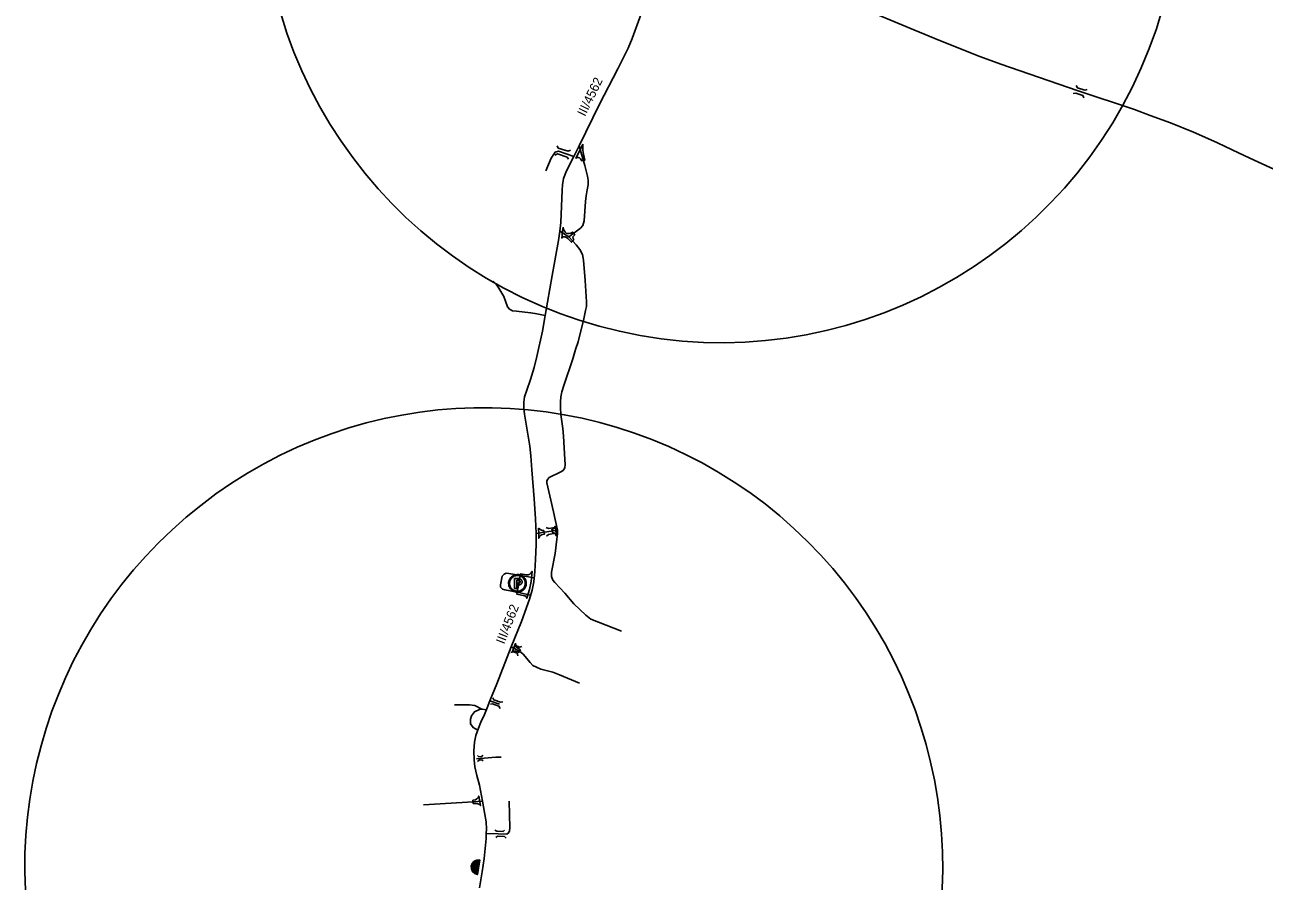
# Model space of a CAD drawing. Extents: x -546703 to -534152, y -1046534 to -1035676.
# Drawn here: x -544141 to -542791, y -1041629 to -1040697 of the extents above; entities that cross this region are included whole.
import ezdxf

# ---------------------------------------------------------------- set-up
doc = ezdxf.new("R2010")
doc.units = 0
for name, color, linetype in [('Vrstva 11', 7, 'Continuous'), ('Vrstva 14', 7, 'Continuous'), ('Vrstva 19', 7, 'Continuous'), ('Vrstva 23', 7, 'Continuous'), ('Vrstva 26', 7, 'Continuous'), ('Vrstva 4', 7, 'Continuous'), ('Vrstva 46', 7, 'Continuous'), ('Vrstva 7', 7, 'Continuous'), ('Vrstva 8', 7, 'Continuous')]:
    doc.layers.add(name, color=color, linetype=linetype)

msp = doc.modelspace()

# ---------------------------------------------------------------- linework, layer by layer
at = {"layer": 'Vrstva 11'}
for points in [[(-543542.6, -1041327.3), (-543529.7, -1041339.7), (-543524, -1041343.8), (-543490.8, -1041357.1)], [(-543706.6, -1041546), (-543652.5, -1041542.9), (-543642.2, -1041542.3)]]:
    msp.add_lwpolyline(points, dxfattribs=at)
msp.add_lwpolyline([(-543652.6, -1041541.2), (-543649.9, -1041540.7), (-543648.4, -1041539.8), (-543647, -1041538.3), (-543646.3, -1041536.6), (-543645.2, -1041542.9), (-543644.4, -1041547), (-543645.6, -1041545.8), (-543647.1, -1041545.2), (-543648.9, -1041544.8), (-543652.5, -1041544.7)], close=True, dxfattribs=at)
at = {"layer": 'Vrstva 14'}
msp.add_line((-543634, -1041432.8), (-543623.6, -1041436.7), dxfattribs=at)
msp.add_lwpolyline([(-543648.8, -1041495.9), (-543627.5, -1041494.1), (-543624.5, -1041494.1), (-543621.9, -1041494.4)], dxfattribs=at)
at = {"layer": 'Vrstva 19'}
msp.add_lwpolyline([(-543604, -1041312.4), (-543604.8, -1041316.6), (-543595.9, -1041318.5), (-543594.7, -1041319.2), (-543594.1, -1041320.1), (-543594, -1041321.2), (-543591, -1041311.7), (-543589.3, -1041303), (-543588.2, -1041291.9), (-543589.4, -1041294), (-543590.5, -1041294.9), (-543592.5, -1041295.6), (-543594.1, -1041295.5), (-543600.7, -1041294.5), (-543603.4, -1041309.2)], close=True, dxfattribs=at)
at = {"layer": 'Vrstva 23'}
for points in [[(-543654.4, -1041612.9), (-543653.3, -1041609.9), (-543651.2, -1041607.6), (-543648.3, -1041606.3), (-543645.1, -1041606.2), (-543647.7, -1041622.2), (-543650.6, -1041621.1), (-543653, -1041618.9), (-543654.3, -1041616)], [(-543653.8, -1041613), (-543652.8, -1041610.2), (-543650.8, -1041608.1), (-543648.2, -1041606.9), (-543645.8, -1041606.8), (-543648.1, -1041621.3), (-543650.3, -1041620.5), (-543652.5, -1041618.6), (-543653.7, -1041615.9)], [(-543653.2, -1041613.1), (-543652.3, -1041610.6), (-543650.4, -1041608.6), (-543648, -1041607.5), (-543646.6, -1041607.4), (-543648.6, -1041620.5), (-543650, -1041620), (-543652, -1041618.2), (-543653.1, -1041615.8)], [(-543652.6, -1041613.2), (-543651.7, -1041610.9), (-543650.1, -1041609.1), (-543647.9, -1041608.1), (-543647.3, -1041608), (-543649.1, -1041619.7), (-543649.7, -1041619.5), (-543651.5, -1041617.8), (-543652.5, -1041615.6)], [(-543652, -1041613.3), (-543651.2, -1041611.2), (-543649.7, -1041609.6), (-543648, -1041608.8), (-543649.6, -1041618.8), (-543651, -1041617.5), (-543651.9, -1041615.5)], [(-543651.4, -1041613.4), (-543650.7, -1041611.5), (-543649.4, -1041610.1), (-543648.8, -1041609.8), (-543650, -1041617.6), (-543650.5, -1041617.1), (-543651.3, -1041615.3)], [(-543650.8, -1041613.5), (-543650.2, -1041611.8), (-543649.6, -1041611.2), (-543650.3, -1041616), (-543650.7, -1041615.2)]]:
    msp.add_lwpolyline(points, close=True, dxfattribs=at)
at = {"layer": 'Vrstva 26'}
for centre, start, end in [((-543382.4, -1040542.8), 99.089, 344.2283), ((-543640.8, -1041613.6), 265.1835, 199.2198)]:
    msp.add_arc(centre, 500, start, end, dxfattribs=at)
at = {"layer": 'Vrstva 4'}
msp.add_lwpolyline([(-543469.2, -1040684.5), (-543479.2, -1040711.6), (-543483.6, -1040721.9), (-543494.6, -1040744.4), (-543514.7, -1040782.9), (-543537, -1040828.6), (-543542.7, -1040840.1), (-543550.5, -1040855.8), (-543554, -1040864.1), (-543555.1, -1040870.8), (-543555.5, -1040876.8), (-543556.8, -1040912), (-543557.8, -1040921.3), (-543559.4, -1040931.6), (-543566.2, -1040969.5), (-543573.8, -1041013.1), (-543576.9, -1041030.3), (-543582.9, -1041058), (-543585.7, -1041069.8), (-543590, -1041082.9), (-543593.8, -1041094.4), (-543596.3, -1041101.8), (-543597.3, -1041107.7), (-543597.3, -1041114.3), (-543596.4, -1041120.7), (-543590.7, -1041155.6), (-543589.5, -1041166.2), (-543588.4, -1041181.3), (-543585.9, -1041213), (-543584.4, -1041234.5), (-543583.8, -1041250.8), (-543583.8, -1041262.7), (-543584.4, -1041279.1), (-543585.2, -1041292.1), (-543586.4, -1041303.4), (-543588, -1041312.4), (-543591.1, -1041322.2), (-543599.7, -1041346.4), (-543610.8, -1041374.2), (-543626.7, -1041414.5), (-543634, -1041432.8), (-543637.1, -1041440.6), (-543639.9, -1041447.7), (-543643.8, -1041456), (-543646.5, -1041462.7), (-543649.5, -1041470.7), (-543650.9, -1041478), (-543651.5, -1041487.2), (-543651.1, -1041497.1), (-543650.4, -1041504.8), (-543648.2, -1041514.2), (-543645.5, -1041524.7), (-543642.2, -1041542.3), (-543639.9, -1041554.6), (-543638.1, -1041564.8), (-543637.9, -1041572.8), (-543638.1, -1041577.2), (-543638.3, -1041582.8), (-543640.5, -1041604.7), (-543642.5, -1041619.1), (-543645.6, -1041636.5)], dxfattribs=at)
at = {"layer": 'Vrstva 46'}
for points in [[(-543604.1, -1041295.3), (-543604.9, -1041295.4), (-543606.1, -1041295.5), (-543607.3, -1041295.9), (-543608.4, -1041296.3), (-543609.4, -1041297), (-543610.4, -1041297.7), (-543611.3, -1041298.5), (-543612, -1041299.5), (-543612.6, -1041300.5), (-543613.1, -1041301.7), (-543613.5, -1041302.8), (-543613.7, -1041304), (-543613.7, -1041305.2), (-543613.6, -1041306.4), (-543613.3, -1041307.6), (-543612.9, -1041308.8), (-543612.4, -1041309.9), (-543611.7, -1041310.9), (-543610.9, -1041311.8), (-543609.9, -1041312.6), (-543608.9, -1041313.2), (-543607.8, -1041313.8), (-543606.7, -1041314.2), (-543605.5, -1041314.4), (-543604.3, -1041314.5), (-543603.1, -1041314.5), (-543601.9, -1041314.3), (-543600.7, -1041313.9), (-543599.6, -1041313.4), (-543598.6, -1041312.8), (-543597.6, -1041312), (-543596.8, -1041311.2), (-543596.1, -1041310.2), (-543595.5, -1041309.1), (-543595, -1041308), (-543594.7, -1041306.9), (-543594.5, -1041305.6), (-543594.5, -1041304.4), (-543594.6, -1041303.2), (-543594.9, -1041302), (-543595.4, -1041300.9), (-543595.9, -1041299.8), (-543596.7, -1041298.9), (-543597.5, -1041298), (-543598.4, -1041297.2), (-543599.4, -1041296.5), (-543600.5, -1041296), (-543601.7, -1041295.6), (-543602.9, -1041295.4), (-543604.1, -1041295.3)], [(-543595.5, -1041304.9), (-543595.5, -1041303.8), (-543595.7, -1041302.8), (-543596.1, -1041301.7), (-543596.5, -1041300.7), (-543597.1, -1041299.8), (-543597.8, -1041299), (-543598.6, -1041298.2), (-543599.5, -1041297.6), (-543600.5, -1041297.1), (-543601.5, -1041296.7), (-543602.6, -1041296.4), (-543603.6, -1041296.3), (-543604.7, -1041296.3), (-543605.8, -1041296.5), (-543606.9, -1041296.7), (-543607.9, -1041297.2), (-543608.8, -1041297.7), (-543609.7, -1041298.4), (-543610.5, -1041299.1), (-543611.2, -1041300), (-543611.7, -1041300.9), (-543612.2, -1041301.9), (-543612.5, -1041303), (-543612.7, -1041304), (-543612.7, -1041305.1), (-543612.6, -1041306.2), (-543612.4, -1041307.3), (-543612.1, -1041308.3), (-543611.6, -1041309.3), (-543611, -1041310.2), (-543610.2, -1041311), (-543609.4, -1041311.7), (-543608.5, -1041312.4), (-543607.6, -1041312.9), (-543606.5, -1041313.2), (-543605.5, -1041313.5), (-543604.4, -1041313.6), (-543603.3, -1041313.5), (-543602.2, -1041313.4), (-543601.1, -1041313.1), (-543600.1, -1041312.6), (-543599.2, -1041312.1), (-543598.3, -1041311.4), (-543597.6, -1041310.6), (-543596.9, -1041309.7), (-543596.4, -1041308.8), (-543595.9, -1041307.8), (-543595.6, -1041306.7), (-543595.5, -1041305.7), (-543595.5, -1041304.9)], [(-543604.1, -1041296.3), (-543603.4, -1041296.3), (-543602.3, -1041296.5), (-543601.2, -1041296.8), (-543600.2, -1041297.2), (-543599.3, -1041297.8), (-543598.4, -1041298.4), (-543597.6, -1041299.2), (-543597, -1041300), (-543596.4, -1041301), (-543596, -1041302), (-543595.7, -1041303), (-543595.5, -1041304.1), (-543595.5, -1041305.2), (-543595.6, -1041306.3), (-543595.8, -1041307.4), (-543596.2, -1041308.4), (-543596.7, -1041309.4), (-543597.3, -1041310.3), (-543598, -1041311.1), (-543598.8, -1041311.8), (-543599.7, -1041312.4), (-543600.7, -1041312.9), (-543601.8, -1041313.3), (-543602.8, -1041313.5), (-543603.9, -1041313.6), (-543605, -1041313.5), (-543606.1, -1041313.4), (-543607.1, -1041313), (-543608.1, -1041312.6), (-543609.1, -1041312), (-543609.9, -1041311.3), (-543610.7, -1041310.6), (-543611.3, -1041309.7), (-543611.9, -1041308.7), (-543612.3, -1041307.7), (-543612.6, -1041306.7), (-543612.7, -1041305.6), (-543612.7, -1041304.5), (-543612.6, -1041303.4), (-543612.3, -1041302.3), (-543612, -1041301.3), (-543611.4, -1041300.4), (-543610.8, -1041299.5), (-543610.1, -1041298.7), (-543609.2, -1041298), (-543608.3, -1041297.4), (-543607.3, -1041296.9), (-543606.3, -1041296.6), (-543605.2, -1041296.4), (-543604.1, -1041296.3)], [(-543602.5, -1041299.8), (-543607.2, -1041299.8), (-543607.2, -1041310.6), (-543604.9, -1041310.6), (-543604.9, -1041304.9)], [(-543604.9, -1041304.9), (-543604.9, -1041301.5)], [(-543604.9, -1041301.5), (-543603, -1041301.5)], [(-543603, -1041304.9), (-543604.9, -1041304.9)], [(-543604.9, -1041304.9), (-543604.9, -1041306.7)], [(-543604.1, -1041295.3), (-543604.1, -1041296.3)], [(-543604.1, -1041296.3), (-543604.1, -1041295.3)], [(-543603, -1041301.5), (-543602.9, -1041301.5), (-543602.9, -1041301.5), (-543602.4, -1041301.6), (-543602.3, -1041301.7), (-543602.1, -1041301.8), (-543601.9, -1041301.9), (-543601.8, -1041302.1), (-543601.6, -1041302.2), (-543601.4, -1041302.5), (-543601.3, -1041302.7), (-543601.2, -1041303.2), (-543601.2, -1041303.3), (-543601.3, -1041303.7), (-543601.4, -1041303.9), (-543601.6, -1041304.2), (-543601.7, -1041304.3), (-543601.8, -1041304.4), (-543602.1, -1041304.6), (-543602.3, -1041304.7), (-543602.5, -1041304.8), (-543602.9, -1041304.9), (-543603, -1041304.9)], [(-543602.5, -1041306.7), (-543602, -1041306.7), (-543601.7, -1041306.6), (-543601.4, -1041306.5), (-543601.2, -1041306.4), (-543601, -1041306.3), (-543600.8, -1041306.2), (-543600.6, -1041306.1), (-543600.3, -1041305.9), (-543600.1, -1041305.7), (-543600, -1041305.6), (-543599.8, -1041305.4), (-543599.6, -1041305.1), (-543599.5, -1041304.9), (-543599.4, -1041304.7), (-543599.3, -1041304.5), (-543599.2, -1041304.3), (-543599.1, -1041304), (-543599, -1041303.6), (-543599, -1041303.3), (-543599, -1041303), (-543599.1, -1041302.6), (-543599.1, -1041302.5), (-543599.2, -1041302.2), (-543599.3, -1041302), (-543599.5, -1041301.6), (-543599.6, -1041301.4), (-543599.8, -1041301.1), (-543600, -1041300.9), (-543600.1, -1041300.8), (-543600.3, -1041300.6), (-543600.6, -1041300.4), (-543600.8, -1041300.3), (-543601, -1041300.2), (-543601.2, -1041300.1), (-543601.4, -1041300), (-543601.6, -1041299.9), (-543602, -1041299.8), (-543602.5, -1041299.8)], [(-543604.9, -1041306.7), (-543602.5, -1041306.7)]]:
    msp.add_lwpolyline(points, dxfattribs=at)
at = {"layer": 'Vrstva 7'}
msp.add_line((-543560.4, -1041247), (-543583.8, -1041250.8), dxfattribs=at)
for points in [[(-543211.3, -1040685.9), (-543172.1, -1040702.1), (-543143.1, -1040714.1), (-543100.5, -1040731.1), (-543077.4, -1040739.5), (-542994.3, -1040768.3), (-542931.9, -1040789), (-542914.9, -1040795.3), (-542892.8, -1040803.5), (-542867.7, -1040813.5), (-542851.9, -1040820.3), (-542841.5, -1040825), (-542825.6, -1040832.7), (-542806.1, -1040841.8), (-542770.5, -1040858.1)], [(-543537, -1040828.6), (-543530.6, -1040850), (-543527.6, -1040861.3), (-543527, -1040866), (-543527, -1040870.9), (-543528, -1040876.2), (-543529.3, -1040883), (-543530, -1040889), (-543531.5, -1040910.1), (-543532.9, -1040915.1), (-543535.3, -1040918), (-543548, -1040927.7)], [(-543573.3, -1040855.5), (-543567.4, -1040841.8), (-543563, -1040835.3), (-543559.4, -1040834.3), (-543542.7, -1040840.1)], [(-543557.8, -1040921.3), (-543548, -1040927.7), (-543543.9, -1040932.2), (-543540, -1040936.4), (-543536, -1040941.5), (-543533.1, -1040946.9), (-543532.2, -1040952.8), (-543530.4, -1040975.1), (-543528.9, -1040998.2), (-543529, -1041003.4), (-543529.8, -1041007.7), (-543531.8, -1041016.9), (-543538.1, -1041041.9), (-543540.7, -1041050.1), (-543543.9, -1041060.3), (-543553.6, -1041089.5), (-543555.7, -1041096.4), (-543556.8, -1041101.9), (-543557.3, -1041107.3), (-543557.2, -1041113.9), (-543556.8, -1041121), (-543554.7, -1041136.3), (-543553.8, -1041144.7), (-543552.3, -1041170.1), (-543552.1, -1041175.6), (-543552.6, -1041179.2), (-543554.4, -1041181.9), (-543557.4, -1041183.7), (-543569.5, -1041189.8), (-543571.3, -1041191.7), (-543572, -1041193.6), (-543572, -1041195.5), (-543567.8, -1041214.4), (-543564.8, -1041227), (-543560.4, -1041247), (-543560.3, -1041251), (-543561, -1041256.8), (-543563, -1041272.6), (-543567, -1041292.7), (-543567, -1041297.5), (-543565.7, -1041301.5), (-543563.3, -1041304.1), (-543552.4, -1041315.8), (-543542.6, -1041327.3)], [(-543630.7, -1040975.8), (-543627.3, -1040979), (-543624.5, -1040983.5), (-543618.9, -1040992.7), (-543617, -1040997.6), (-543615, -1041003.8), (-543612.7, -1041006.4), (-543609.5, -1041008), (-543605.1, -1041008.5), (-543589.7, -1041010.2), (-543584.9, -1041011.1), (-543581, -1041011.8), (-543573.8, -1041013.1)], [(-543585.9, -1041298.8), (-543600.5, -1041296.5), (-543613.5, -1041294.2), (-543616.4, -1041294), (-543618.7, -1041294.8), (-543620.7, -1041297.2), (-543622.6, -1041306.4), (-543622.5, -1041309.1), (-543620.4, -1041311.4), (-543617.9, -1041312.1), (-543604.4, -1041314.6), (-543589.8, -1041317.9)], [(-543610.8, -1041374.2), (-543601.7, -1041378.9), (-543597.8, -1041382.1), (-543590.2, -1041391.3), (-543587.2, -1041394.3), (-543583.3, -1041396.4), (-543578.6, -1041398.3), (-543565.7, -1041401.5), (-543558.2, -1041404.4), (-543536.4, -1041413.8)], [(-543672.6, -1041437.3), (-543656.2, -1041437.3), (-543650.4, -1041438.1), (-543642.8, -1041442)], [(-543647.3, -1041464.8), (-543652.4, -1041462.1), (-543655.4, -1041457.9), (-543655.2, -1041453), (-543654.3, -1041449.2), (-543650.9, -1041444.8), (-543645.6, -1041442.2), (-543642.3, -1041441.9), (-543638, -1041442.7)], [(-543638.1, -1041577.2), (-543625.1, -1041577.7), (-543615.6, -1041578), (-543613.5, -1041576.4), (-543612.6, -1041574.3), (-543612.2, -1041571.3), (-543613, -1041542.2)]]:
    msp.add_lwpolyline(points, dxfattribs=at)
for points in [[(-543532.8, -1040826.8), (-543534.4, -1040829.9), (-543540.3, -1040841.9), (-543539.2, -1040841.3), (-543537.9, -1040841.1), (-543536.5, -1040841.5), (-543535.3, -1040842.5), (-543534.1, -1040844.6), (-543530.6, -1040843.9), (-543532.2, -1040837.6), (-543532.8, -1040833), (-543532.8, -1040830.1)], [(-543554.3, -1040916.9), (-543554.9, -1040921.7), (-543555.9, -1040928.9), (-543555.1, -1040927.9), (-543553.9, -1040927.4), (-543552.2, -1040927.6), (-543550.6, -1040928.3), (-543549.2, -1040929.4), (-543545.2, -1040933.4), (-543542.7, -1040930.9), (-543543.5, -1040929.3), (-543543.6, -1040927.7), (-543542.8, -1040926.5), (-543541.7, -1040925.2), (-543543.8, -1040922.3), (-543546, -1040923.7), (-543547.7, -1040923.9), (-543549.5, -1040924), (-543551, -1040923.4), (-543552.2, -1040922.3), (-543553.2, -1040920.8), (-543553.8, -1040919.4)], [(-543581, -1041244.7), (-543580.8, -1041250.8), (-543580.8, -1041255.8), (-543580, -1041254), (-543579.1, -1041253), (-543577.8, -1041252.2), (-543574.7, -1041251.4), (-543575.4, -1041247.4), (-543577.1, -1041247.3), (-543578.7, -1041246.8), (-543579.7, -1041246.1)], [(-543563.1, -1041242.6), (-543562.1, -1041247.2), (-543562, -1041250.9), (-543562.2, -1041252.9), (-543562.7, -1041251.5), (-543563.5, -1041250.6), (-543564.3, -1041250.1), (-543565.6, -1041249.9), (-543566.5, -1041246), (-543564.7, -1041245.4), (-543563.8, -1041244.7), (-543563.3, -1041243.6)], [(-543600.7, -1041377.4), (-543604.8, -1041374.9), (-543605.8, -1041373.9), (-543606.5, -1041372.7), (-543606.5, -1041371.3), (-543608, -1041375.3), (-543609.8, -1041379.8), (-543609, -1041379.1), (-543608.1, -1041378.7), (-543606.2, -1041378.8), (-543602.7, -1041380.4)]]:
    msp.add_lwpolyline(points, close=True, dxfattribs=at)
at = {"layer": 'Vrstva 8'}
for points in [[(-542995.3, -1040762.8), (-542994.1, -1040765.1), (-542986, -1040767.8), (-542983.3, -1040767)], [(-542998.7, -1040771.5), (-542995.6, -1040770.9), (-542988.2, -1040773.5), (-542987.2, -1040776.2)], [(-543560.9, -1040828.4), (-543559.6, -1040830.9), (-543548.7, -1040834.4), (-543546.2, -1040833.3)], [(-543563.2, -1040838.6), (-543560.6, -1040837.1), (-543550, -1040840.7), (-543548.6, -1040842.9)], [(-543572.8, -1041244.1), (-543570.4, -1041245.3), (-543563, -1041244), (-543561.5, -1041242)], [(-543572.5, -1041253.7), (-543570.2, -1041251.7), (-543562.6, -1041250.4), (-543560.8, -1041252.1)], [(-543606.2, -1041370), (-543605.8, -1041372.6), (-543601.7, -1041374.5), (-543599.2, -1041373.8)], [(-543611.4, -1041380.4), (-543608.5, -1041379.6), (-543604.5, -1041381.1), (-543603.7, -1041383.7)], [(-543633.5, -1041436.7), (-543631.2, -1041436), (-543624.3, -1041438.8), (-543622.9, -1041441.1)], [(-543630.9, -1041429.7), (-543629.9, -1041431.7), (-543622.6, -1041434.5), (-543619.9, -1041433.9)], [(-543647.7, -1041492.5), (-543646.3, -1041493.7), (-543643, -1041493.4), (-543641.8, -1041492.1)], [(-543647.5, -1041498.8), (-543645.9, -1041497.6), (-543642.7, -1041497.3), (-543641.4, -1041498.3)], [(-543628.7, -1041573.6), (-543626.7, -1041575), (-543619.7, -1041575.2), (-543618.1, -1041573.6)], [(-543627.5, -1041581.9), (-543625.7, -1041580.4), (-543618.1, -1041580.7), (-543616.5, -1041582.5)]]:
    msp.add_lwpolyline(points, dxfattribs=at)

# ---------------------------------------------------------------- texts
at = {"layer": 'Vrstva 4'}
for rotation, p in [(63.8954, (-543530.5, -1040797.1)), (68.5662, (-543618.5, -1041371.8))]:
    msp.add_text('III/4562', height=10, rotation=rotation, dxfattribs=at).set_placement(p)

doc.saveas('drawing.dxf')
